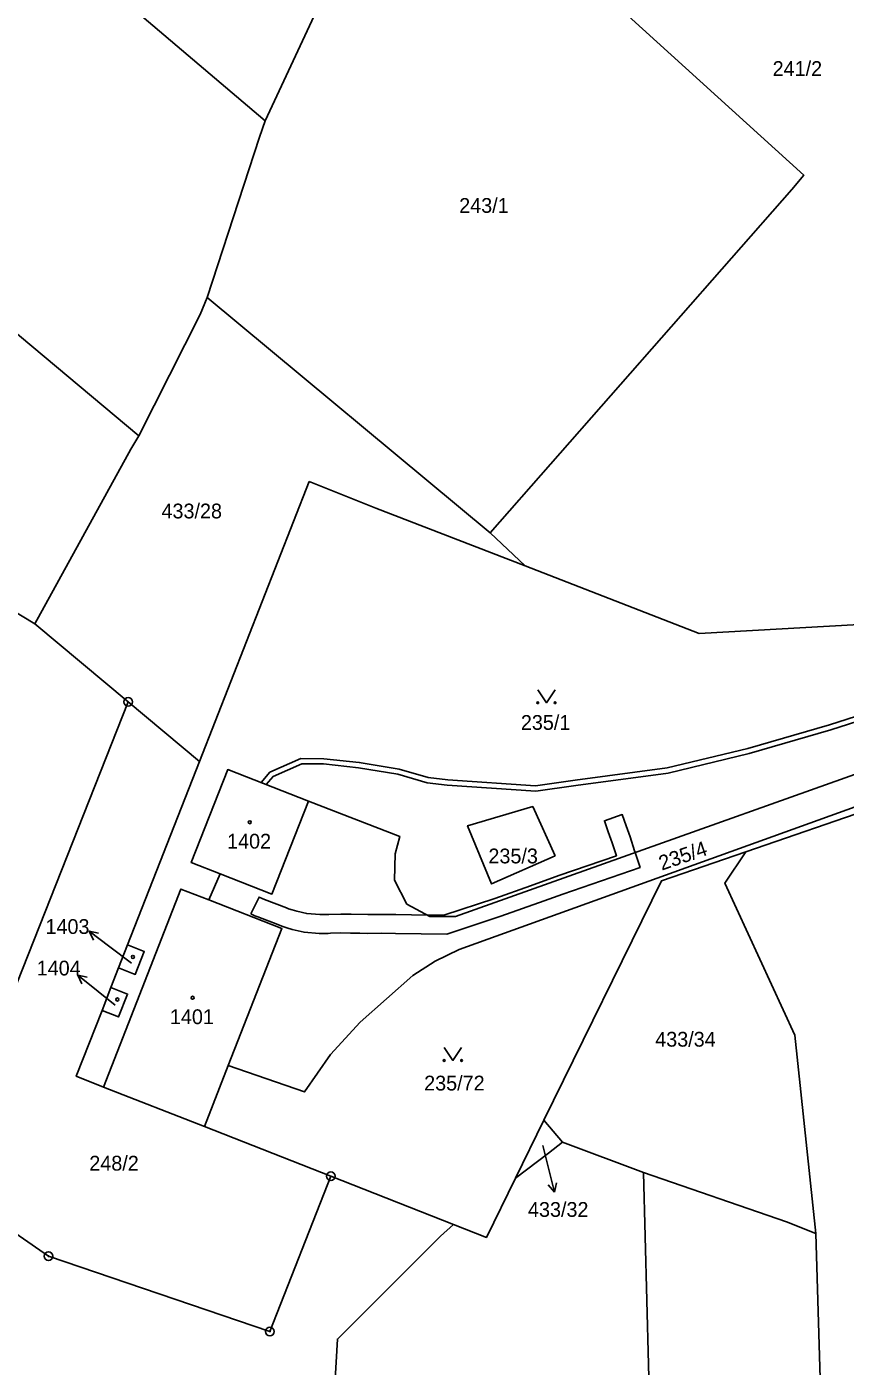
# Model space of a CAD drawing. Extents: x -680203 to -673936, y -1102717 to -1093650.
# Drawn here: x -679609.4 to -679515.3, y -1098356.8 to -1098202.8 of the extents above; entities that cross this region are included whole.
import ezdxf

# ---------------------------------------------------------------- set-up
doc = ezdxf.new("R2010")
doc.units = 0
for name, color, linetype in [('SOxx02xx_Koleje_param další_Popis10', 7, 'Continuous'), ('SOxx02xx_Staničení_Popis10', 7, 'Continuous'), ('SOxxxxxx_Koleje_hlavní_body_Popis10', 7, 'Continuous'), ('SOxxxxxx_Koleje_LN_parametry_Popis10', 7, 'Continuous'), ('SOxxxxxx_Koleje_param další_Popis10', 7, 'Continuous'), ('SOxxxxxx_Osa_bod_P', 7, 'Continuous'), ('x_prac', 7, 'Continuous')]:
    doc.layers.add(name, color=color, linetype=linetype)

msp = doc.modelspace()

# ---------------------------------------------------------------- linework, layer by layer
at = {"layer": 'SOxx02xx_Koleje_param další_Popis10'}
for centre, radius in [((-679597.76, -1098280.39), 0.5), ((-679597.76, -1098280.39), 0.0303), ((-679574.44, -1098334.93), 0.5), ((-679574.44, -1098334.93), 0.0303), ((-679606.91, -1098344.12), 0.5), ((-679606.91, -1098344.12), 0.0303), ((-679581.46, -1098352.79), 0.5), ((-679581.46, -1098352.79), 0.0303)]:
    msp.add_circle(centre, radius, dxfattribs=at)
at = {"layer": 'SOxx02xx_Staničení_Popis10'}
for p, q in [((-679599.85, -1098308.57), (-679602.25, -1098306.76)), ((-679602.25, -1098306.76), (-679601.15, -1098306.97)), ((-679602.25, -1098306.76), (-679601.75, -1098307.77)), ((-679597.38, -1098310.43), (-679599.85, -1098308.57)), ((-679601.22, -1098313.69), (-679603.55, -1098311.8)), ((-679603.55, -1098311.8), (-679602.46, -1098312.04)), ((-679603.55, -1098311.8), (-679603.09, -1098312.82)), ((-679599.26, -1098315.26), (-679601.22, -1098313.69)), ((-679550.09, -1098331.39), (-679549.46, -1098333.85)), ((-679549.46, -1098333.85), (-679548.73, -1098336.76)), ((-679548.73, -1098336.76), (-679549.46, -1098335.91)), ((-679548.73, -1098336.76), (-679548.49, -1098335.67))]:
    msp.add_line(p, q, dxfattribs=at)
at = {"layer": 'SOxxxxxx_Koleje_hlavní_body_Popis10'}
for points in [[(-679550.66, -1098278.99), (-679549.66, -1098280.49), (-679548.66, -1098278.99)], [(-679561.42, -1098320.12), (-679560.42, -1098321.62), (-679559.42, -1098320.12)]]:
    msp.add_lwpolyline(points, dxfattribs=at)
for centre in [(-679550.66, -1098280.49), (-679548.66, -1098280.49), (-679561.42, -1098321.62), (-679559.42, -1098321.62)]:
    msp.add_circle(centre, 0.1, dxfattribs=at)
at = {"layer": 'SOxxxxxx_Koleje_LN_parametry_Popis10'}
msp.add_lwpolyline([(-679505.76, -1098279.4), (-679517.12, -1098283.02), (-679526.51, -1098285.75), (-679535.78, -1098287.98), (-679546.34, -1098289.4), (-679550.91, -1098290.04), (-679561, -1098289.36), (-679563.26, -1098289.1), (-679566.6, -1098288.14), (-679571.19, -1098287.36), (-679575.26, -1098286.93), (-679577.89, -1098286.91), (-679581.45, -1098288.47), (-679582.47, -1098289.68), (-679581.88, -1098289.91), (-679581.09, -1098288.97), (-679577.77, -1098287.51), (-679575.3, -1098287.53), (-679571.27, -1098287.96), (-679566.74, -1098288.72), (-679563.38, -1098289.7), (-679561.06, -1098289.96), (-679550.89, -1098290.64), (-679546.26, -1098290), (-679535.66, -1098288.58), (-679526.35, -1098286.33), (-679516.94, -1098283.6), (-679505.6, -1098279.98)], dxfattribs=at)
msp.add_lwpolyline([(-679583.64, -1098304.78), (-679583.18, -1098305.01), (-679582.86, -1098305.12), (-679580.55, -1098305.99), (-679580.08, -1098306.19), (-679579.52, -1098306.38), (-679578.88, -1098306.56), (-679577.53, -1098306.87), (-679575.8, -1098307.01), (-679574.77, -1098307.01), (-679574.5, -1098307), (-679573.31, -1098306.96), (-679572.18, -1098306.97), (-679571.12, -1098307), (-679570.18, -1098307.01), (-679568.66, -1098306.99), (-679567.03, -1098307.01), (-679561.12, -1098307.09), (-679554.9, -1098305.02), (-679549.91, -1098303.25), (-679547.76, -1098302.49), (-679538.89, -1098299.43), (-679539.47, -1098297.72), (-679539.54, -1098297.52), (-679540.05, -1098295.92), (-679540.51, -1098294.64), (-679540.95, -1098293.36), (-679542.99, -1098294.06), (-679542.57, -1098295.32), (-679542.11, -1098296.6), (-679541.62, -1098298.09), (-679548.23, -1098300.37), (-679551.51, -1098301.53), (-679555.6, -1098302.98), (-679561.46, -1098304.93), (-679563.36, -1098304.9), (-679566.97, -1098304.85), (-679568.66, -1098304.83), (-679570.18, -1098304.85), (-679572.1, -1098304.81), (-679573.31, -1098304.8), (-679574.66, -1098304.84), (-679574.83, -1098304.85), (-679575.7, -1098304.85), (-679577.21, -1098304.73), (-679578.36, -1098304.46), (-679578.88, -1098304.32), (-679579.3, -1098304.17), (-679579.54, -1098304.07), (-679582.08, -1098303.1), (-679582.34, -1098303.01), (-679582.7, -1098302.84)], close=True, dxfattribs=at)
at = {"layer": 'SOxxxxxx_Koleje_param další_Popis10'}
for centre in [(-679583.77, -1098294.23), (-679597.21, -1098309.72), (-679598.99, -1098314.61), (-679590.34, -1098314.41)]:
    msp.add_circle(centre, 0.175, dxfattribs=at)
at = {"layer": 'x_prac'}
for p, q in [((-679596.54, -1098249.82), (-679671.29, -1098187.06)), ((-679588.65, -1098233.9), (-679556.13, -1098260.95)), ((-679589.55, -1098287.24), (-679576.95, -1098255.06)), ((-679576.95, -1098255.06), (-679569.27, -1098258.11)), ((-679569.27, -1098258.11), (-679552.12, -1098264.75)), ((-679552.12, -1098264.75), (-679556.13, -1098260.95)), ((-679620.65, -1098264.04), (-679608.49, -1098271.42)), ((-679608.49, -1098271.42), (-679597.76, -1098280.39)), ((-679597.76, -1098280.39), (-679612.42, -1098317.51)), ((-679597.76, -1098280.39), (-679589.55, -1098287.24)), ((-679597.81, -1098308.34), (-679589.55, -1098287.24)), ((-679499.88, -1098288.37), (-679526.74, -1098297.63)), ((-679588.46, -1098303.17), (-679587.18, -1098300.16)), ((-679598.85, -1098310.98), (-679597.81, -1098308.34)), ((-679599.73, -1098313.23), (-679598.85, -1098310.98)), ((-679600.76, -1098315.86), (-679599.73, -1098313.23)), ((-679588.98, -1098329.22), (-679586.24, -1098322.21)), ((-679588.98, -1098329.22), (-679600.6, -1098324.67)), ((-679549.94, -1098328.5), (-679553.21, -1098335.15)), ((-679547.8, -1098331.03), (-679549.94, -1098328.5)), ((-679574.44, -1098334.93), (-679588.98, -1098329.22)), ((-679538.5, -1098334.5), (-679547.8, -1098331.03)), ((-679581.46, -1098352.79), (-679574.44, -1098334.93)), ((-679560.35, -1098340.47), (-679574.44, -1098334.93))]:
    msp.add_line(p, q, dxfattribs=at)
for points in [[(-679582.01, -1098213.61), (-679615.96, -1098184.76), (-679651.35, -1098154.09)], [(-679563.74, -1098180.17), (-679565.34, -1098182.15), (-679571.26, -1098190.55), (-679582.01, -1098213.61)], [(-679556.13, -1098260.95), (-679521.44, -1098221.48), (-679520.07, -1098219.85), (-679563.74, -1098180.17)], [(-679582.01, -1098213.61), (-679582.67, -1098215.48), (-679588.65, -1098233.9)], [(-679596.54, -1098249.82), (-679589.48, -1098235.84), (-679588.65, -1098233.9)], [(-679608.49, -1098271.42), (-679597.45, -1098251.34), (-679596.54, -1098249.82)], [(-679552.12, -1098264.75), (-679532.08, -1098272.52), (-679489.85, -1098270.17)], [(-679577.03, -1098291.81), (-679566.5, -1098295.86), (-679567.06, -1098297.86), (-679567.11, -1098300.89), (-679565.71, -1098303.64), (-679563.08, -1098305.05), (-679560.1, -1098305.06), (-679493.77, -1098281.45), (-679492.51, -1098280.81)], [(-679586.24, -1098322.21), (-679577.46, -1098325.23), (-679574.5, -1098320.95), (-679571.08, -1098317.22), (-679565.01, -1098311.85), (-679562.44, -1098310.21), (-679559.7, -1098308.85), (-679492.37, -1098284.61), (-679491.3, -1098284.35)], [(-679577.03, -1098291.81), (-679586.31, -1098288.18), (-679590.5, -1098298.87), (-679587.18, -1098300.16)], [(-679587.18, -1098300.16), (-679581.22, -1098302.5), (-679577.03, -1098291.81)], [(-679548.65, -1098298.11), (-679555.97, -1098301.33), (-679558.72, -1098294.63), (-679551.23, -1098292.43), (-679548.65, -1098298.11)], [(-679526.74, -1098297.63), (-679536.41, -1098300.96), (-679549.94, -1098328.5)], [(-679518.69, -1098341.51), (-679521.09, -1098318.7), (-679529.14, -1098301.24), (-679526.74, -1098297.63)], [(-679588.46, -1098303.17), (-679591.69, -1098301.91), (-679600.6, -1098324.67)], [(-679586.24, -1098322.21), (-679580.07, -1098306.45), (-679588.46, -1098303.17)], [(-679598.85, -1098310.98), (-679596.94, -1098311.73), (-679595.9, -1098309.09), (-679597.81, -1098308.34)], [(-679600.76, -1098315.86), (-679598.85, -1098316.61), (-679597.82, -1098313.98), (-679599.73, -1098313.23)], [(-679600.6, -1098324.67), (-679603.73, -1098323.44), (-679600.76, -1098315.86)], [(-679612.42, -1098317.51), (-679614.45, -1098329.66), (-679613.21, -1098339.79), (-679606.91, -1098344.12), (-679581.46, -1098352.79)], [(-679547.8, -1098331.03), (-679549.41, -1098332.27), (-679553.21, -1098335.15)], [(-679540.74, -1098449.36), (-679539.18, -1098432.51), (-679536.96, -1098393.37), (-679538.5, -1098334.5)], [(-679538.5, -1098334.5), (-679522.04, -1098340.16), (-679518.69, -1098341.51)], [(-679560.35, -1098340.47), (-679556.56, -1098341.96), (-679553.21, -1098335.15)], [(-679560.35, -1098340.47), (-679561.84, -1098341.8), (-679573.69, -1098353.65), (-679575.97, -1098393.38), (-679576.29, -1098397.32)], [(-679520.75, -1098451.13), (-679516.58, -1098406.6), (-679517.33, -1098386.31), (-679518.69, -1098341.51)]]:
    msp.add_lwpolyline(points, dxfattribs=at)

# ---------------------------------------------------------------- texts
at = {"layer": 'SOxxxxxx_Osa_bod_P'}
for s, p in [('241/2', (-679523.65, -1098208.43)), ('243/1', (-679559.69, -1098224.17)), ('433/28', (-679593.92, -1098259.3)), ('235/1', (-679552.6, -1098283.61)), ('1402', (-679586.38, -1098297.26)), ('235/3', (-679556.33, -1098298.96)), ('1403', (-679607.26, -1098307.07)), ('1404', (-679608.27, -1098311.85)), ('1401', (-679592.95, -1098317.44)), ('433/34', (-679537.15, -1098320.03)), ('235/72', (-679563.72, -1098325.07)), ('248/2', (-679602.22, -1098334.28)), ('433/32', (-679551.78, -1098339.6))]:
    msp.add_text(s, height=1.7, dxfattribs=at).set_placement(p)
msp.add_text('235/4', height=1.7, rotation=19, dxfattribs=at).set_placement((-679536.39, -1098299.8))

doc.saveas('drawing.dxf')
